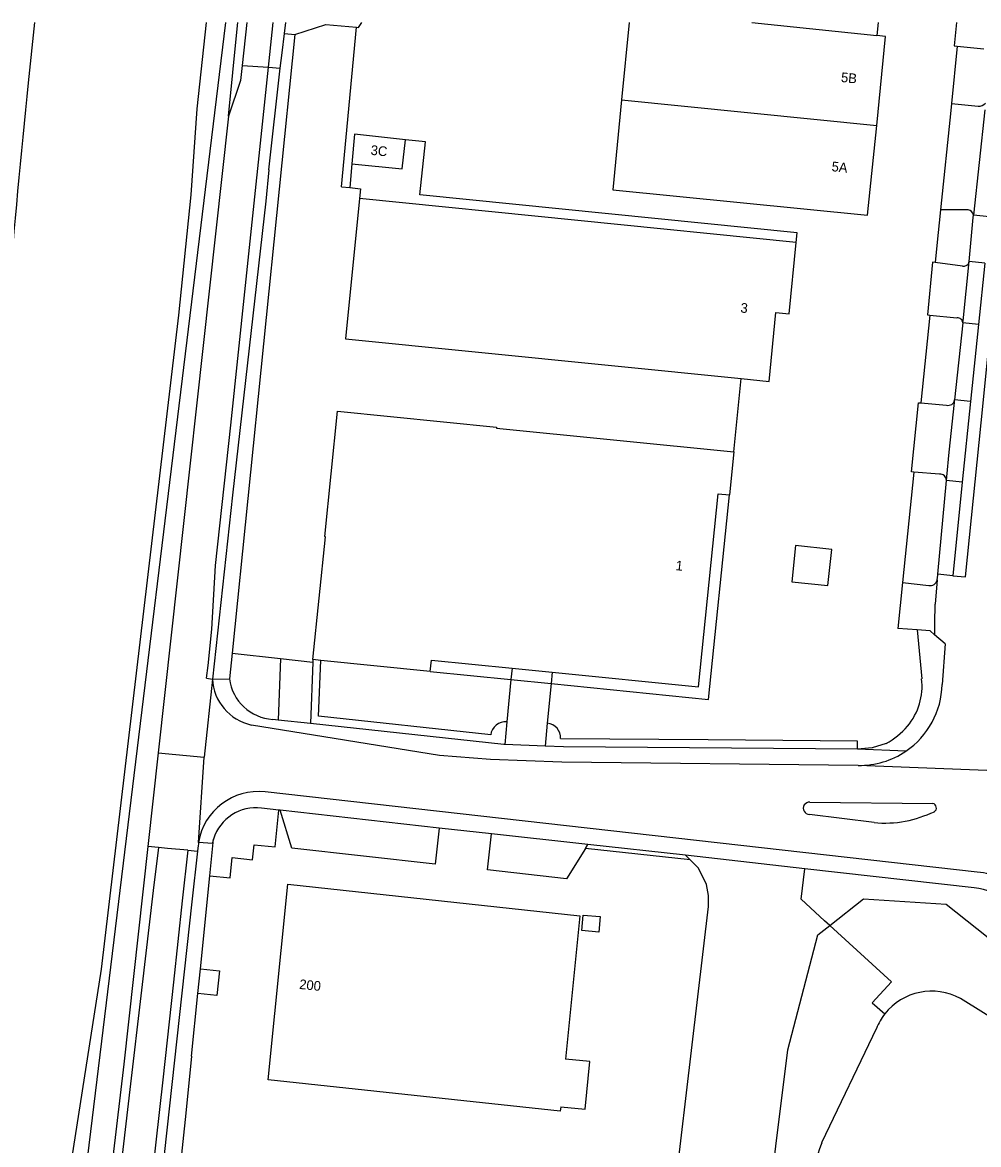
# Model space of a CAD drawing. Extents: x 194485 to 197793, y 468269 to 470822.
# Drawn here: x 195068.9 to 195187.3, y 470683.4 to 470822.3 of the extents above; entities that cross this region are included whole.
import ezdxf

# ---------------------------------------------------------------- set-up
doc = ezdxf.new("R2010")
doc.units = 0
for name, color, linetype in [('BGT begrenzing pand op maaiveld onder overbouw', 7, 'Continuous'), ('BGT grensvlak begroeid terreindeel', 7, 'Continuous'), ('BGT grensvlak onbegroeid terreindeel', 7, 'Continuous'), ('BGT grensvlak onbegroeid terreindeel LR', 7, 'Continuous'), ('BGT grensvlak ondersteunend waterdeel LR', 7, 'Continuous'), ('BGT grensvlak ondersteunend wegdeel', 7, 'Continuous'), ('BGT grensvlak pand deel overbouw', 7, 'Continuous'), ('BGT grensvlak pand op maaiveld', 7, 'Continuous'), ('BGT grensvlak pand op maaiveld LR', 7, 'Continuous'), ('BGT grensvlak vegetatieobject', 7, 'Continuous'), ('BGT grensvlak waterdeel', 7, 'Continuous'), ('BGT grensvlak wegdeel', 7, 'Continuous'), ('BGT tekst huisnummerreeks', 7, 'Continuous')]:
    doc.layers.add(name, color=color, linetype=linetype)

msp = doc.modelspace()

# ---------------------------------------------------------------- linework, layer by layer
at = {"layer": 'BGT begrenzing pand op maaiveld onder overbouw'}
msp.add_line((195129.55, 470742.33), (195134.52, 470741.83), dxfattribs=at)
for points in [[(195134.52, 470741.83), (195152.61, 470740.01), (195155.05, 470763.92), (195156.44, 470763.78)], [(195119.42, 470741.94), (195119.57, 470743.33), (195129.55, 470742.33)]]:
    msp.add_lwpolyline(points, dxfattribs=at)
at = {"layer": 'BGT grensvlak begroeid terreindeel'}
for p, q in [((195094.9, 470744.18), (195094.58, 470741.01)), ((195151.59, 470718.61), (195151.03, 470719.18))]:
    msp.add_line(p, q, dxfattribs=at)
for points in [[(195168.87, 470710.47), (195168.22, 470711.07), (195165.32, 470713.73), (195165.77, 470717.51)], [(195168.87, 470710.47), (195173.05, 470713.76), (195183.29, 470713.11), (195206.25, 470694.88), (195209.33, 470692.98), (195209.99, 470691.54)], [(195134.53, 470532.02), (195143.14, 470543.73), (195159.54, 470567.5), (195161.49, 470571.29), (195158.05, 470579.77), (195152.18, 470593.85), (195151.95, 470603.23), (195154.76, 470623.54), (195163.69, 470695.09), (195167.39, 470709.31), (195168.87, 470710.47)]]:
    msp.add_lwpolyline(points, dxfattribs=at)
at = {"layer": 'BGT grensvlak onbegroeid terreindeel'}
for p, q in [((195102.68, 470820.8), (195094.9, 470744.18)), ((195184.64, 470819.36), (195183.92, 470812.26)), ((195109.73, 470804.76), (195109.47, 470801.83)), ((195181.23, 470786.05), (195180.13, 470775.17)), ((195179.26, 470766.61), (195177.88, 470752.94)), ((195094.9, 470744.18), (195100.9, 470743.53)), ((195104.9, 470743.41), (195104.88, 470743.1)), ((195100.23, 470720.2), (195100.7, 470724.77)), ((195097.44, 470718.62), (195097.63, 470720.46)), ((195097.63, 470720.46), (195100.23, 470720.2)), ((195151.59, 470718.61), (195138.64, 470720.03)), ((195094.66, 470716.36), (195094.92, 470718.88)), ((195094.92, 470718.88), (195097.44, 470718.62)), ((195090.97, 470705.12), (195092.14, 470716.61)), ((195092.14, 470716.61), (195094.66, 470716.36)), ((195089.87, 470694.32), (195090.66, 470702.06)), ((195089.87, 470694.32), (195089.16, 470687.24)), ((195089.16, 470687.24), (195087.08, 470666.83))]:
    msp.add_line(p, q, dxfattribs=at)
for points in [[(195164.69, 470795.05), (195164.81, 470796.25), (195118.11, 470800.96), (195118.85, 470807.5), (195116.36, 470807.77)], [(195109.47, 470801.83), (195110.77, 470801.7), (195110.65, 470800.5)], [(195182.56, 470799.1), (195182.11, 470794.68), (195181.89, 470792.56)], [(195164.16, 470753.03), (195168.64, 470752.57), (195169.1, 470757.05), (195164.62, 470757.51), (195164.16, 470753.03)], [(195126.9, 470734.07), (195105.61, 470736.38), (195105.89, 470743.3)], [(195172.3, 470732.3), (195172.31, 470733.3), (195153.82, 470733.46), (195135.56, 470733.61)], [(195147.73, 470660.73), (195153.86, 470712.82), (195153.87, 470714.19), (195153.61, 470715.54), (195152.62, 470717.57), (195151.59, 470718.61)], [(195090.97, 470705.12), (195093.34, 470704.88), (195093.02, 470701.82), (195090.66, 470702.06)]]:
    msp.add_lwpolyline(points, dxfattribs=at)
for centre, start, end in [((195128.72, 470733.88), 84.4234, 174.1304), ((195133.73, 470733.7), 357.4875, 84.456)]:
    msp.add_arc(centre, 1.83, start, end, dxfattribs=at)
at = {"layer": 'BGT grensvlak onbegroeid terreindeel LR'}
for p, q in [((195108.43, 470801.93), (195110.31, 470821.68)), ((195108.43, 470801.93), (195109.47, 470801.83)), ((195156.98, 470769.12), (195157.89, 470778.2))]:
    msp.add_line(p, q, dxfattribs=at)
at = {"layer": 'BGT grensvlak ondersteunend waterdeel LR'}
msp.add_lwpolyline([(195168.87, 470710.47), (195176.49, 470703.49), (195174.12, 470700.92), (195175.67, 470699.53)], dxfattribs=at)
at = {"layer": 'BGT grensvlak ondersteunend wegdeel'}
for p, q in [((195092.14, 470716.61), (195092.6, 470721.18)), ((195090.66, 470702.06), (195090.97, 470705.12))]:
    msp.add_line(p, q, dxfattribs=at)
at = {"layer": 'BGT grensvlak pand deel overbouw'}
for p, q in [((195119.42, 470741.94), (195129.41, 470740.94)), ((195129.41, 470740.94), (195134.39, 470740.43))]:
    msp.add_line(p, q, dxfattribs=at)
msp.add_lwpolyline([(195134.39, 470740.43), (195153.86, 470738.48), (195156.44, 470763.78)], dxfattribs=at)
at = {"layer": 'BGT grensvlak pand op maaiveld'}
for p, q in [((195144.04, 470822.29), (195143.1, 470812.69)), ((195174.87, 470822.29), (195174.71, 470820.65)), ((195164.69, 470795.05), (195110.65, 470800.5)), ((195156.98, 470769.12), (195156.44, 470763.78)), ((195105.89, 470743.3), (195104.9, 470743.41)), ((195119.42, 470741.94), (195105.89, 470743.3))]:
    msp.add_line(p, q, dxfattribs=at)
for points in [[(195174.67, 470809.51), (195175.77, 470820.53), (195174.71, 470820.65)], [(195143.1, 470812.69), (195142.01, 470801.58), (195173.55, 470798.44), (195174.67, 470809.51)], [(195116.36, 470807.77), (195110.05, 470808.44), (195109.73, 470804.76)], [(195109.73, 470804.76), (195115.96, 470804.18), (195116.36, 470807.77)], [(195110.65, 470800.5), (195108.94, 470783.1), (195157.89, 470778.2)], [(195157.89, 470778.2), (195161.35, 470777.85), (195162.21, 470786.37), (195163.82, 470786.2), (195164.69, 470795.05)], [(195104.9, 470743.41), (195106.46, 470758.61), (195106.36, 470758.62), (195107.96, 470774.14), (195127.61, 470772.17), (195127.6, 470772.07), (195156.98, 470769.12)], [(195135.57, 470688.04), (195135.51, 470687.48), (195099.37, 470691.39), (195101.81, 470715.6), (195137.92, 470711.66), (195136.16, 470693.95)], [(195138.34, 470711.77), (195140.45, 470711.59), (195140.29, 470709.67), (195138.18, 470709.85), (195138.34, 470711.77)], [(195135.57, 470688.04), (195138.61, 470687.74), (195139.18, 470693.65), (195136.16, 470693.95)]]:
    msp.add_lwpolyline(points, dxfattribs=at)
at = {"layer": 'BGT grensvlak pand op maaiveld LR'}
for p, q in [((195159.22, 470822.29), (195174.71, 470820.65)), ((195143.1, 470812.69), (195174.67, 470809.51))]:
    msp.add_line(p, q, dxfattribs=at)
at = {"layer": 'BGT grensvlak vegetatieobject'}
for p, q in [((195094.1, 470822.29), (195070.12, 470625.27)), ((195094.47, 470810.67), (195095.52, 470821.5)), ((195095.52, 470821.5), (195095.6, 470822.29))]:
    msp.add_line(p, q, dxfattribs=at)
at = {"layer": 'BGT grensvlak waterdeel'}
for p, q in [((195070.43, 470822.29), (195069.65, 470814.79)), ((195174.63, 470697.75), (195167.86, 470683.58))]:
    msp.add_line(p, q, dxfattribs=at)
for points in [[(195065.26, 470625.79), (195071.88, 470661.19), (195078.75, 470705.09), (195088.31, 470786.06), (195089.82, 470800.94), (195090.58, 470811.6), (195091.71, 470822.29)], [(195065.26, 470625.79), (195071.88, 470661.19), (195078.75, 470705.09), (195088.31, 470786.06), (195089.82, 470800.94), (195090.58, 470811.6), (195091.71, 470822.29)], [(195201.88, 470689.66), (195193.26, 470696.34), (195185.03, 470701.46)]]:
    msp.add_lwpolyline(points, dxfattribs=at)
for centre, radius, start, end in [((196832.12, 470637.36), 1771.38, 174.25131, 175.12098), ((195181.5, 470694.92), 7.43, 61.6406, 141.7081), ((195181.45, 470694.95), 7.37, 141.6311, 157.6999), ((195223.07, 470664.47), 58.42, 160.9101, 168.0745)]:
    msp.add_arc(centre, radius, start, end, dxfattribs=at)
at = {"layer": 'BGT grensvlak wegdeel'}
for p, q in [((195096.71, 470822.29), (195096.13, 470816.97)), ((195099.84, 470821.08), (195099.97, 470822.29)), ((195101.38, 470820.93), (195101.53, 470822.29)), ((195099.39, 470816.73), (195099.84, 470821.08)), ((195101.38, 470820.93), (195102.68, 470820.8)), ((195184.64, 470819.36), (195187.95, 470819.03)), ((195096.13, 470816.97), (195095.92, 470815.08)), ((195096.13, 470816.97), (195099.39, 470816.73)), ((195099.39, 470816.73), (195100.86, 470816.61)), ((195099.44, 470804.04), (195100.86, 470816.61)), ((195095.92, 470815.08), (195094.47, 470810.67)), ((195183.92, 470812.26), (195183.83, 470811.4)), ((195183.92, 470812.26), (195187.23, 470811.92)), ((195094.47, 470810.67), (195085.74, 470731.87)), ((195183.83, 470811.4), (195182.56, 470799.1)), ((195188.04, 470811.46), (195186.64, 470798.44)), ((195185.98, 470799.07), (195182.56, 470799.1)), ((195188.64, 470798.23), (195186.64, 470798.44)), ((195185.28, 470792.12), (195181.89, 470792.56)), ((195185.36, 470785.35), (195186.13, 470792.67)), ((195188.05, 470792.48), (195186.13, 470792.67)), ((195188.05, 470792.48), (195187.27, 470784.9)), ((195181.23, 470786.05), (195184.61, 470785.7)), ((195185.33, 470785.1), (195185.36, 470785.35)), ((195185.33, 470785.1), (195184.32, 470775.55)), ((195187.27, 470784.9), (195185.33, 470785.1)), ((195187.27, 470784.9), (195186.3, 470775.35)), ((195184.29, 470775.24), (195184.32, 470775.55)), ((195186.3, 470775.35), (195184.32, 470775.55)), ((195180.13, 470775.17), (195183.32, 470774.9)), ((195186.3, 470775.35), (195185.27, 470765.38)), ((195182.45, 470766.36), (195179.26, 470766.61)), ((195183.31, 470765.59), (195183.35, 470766.01)), ((195182.23, 470753.96), (195183.31, 470765.59)), ((195185.27, 470765.38), (195183.31, 470765.59)), ((195185.27, 470765.38), (195184.08, 470753.79)), ((195182.16, 470753.26), (195181.89, 470750.26)), ((195182.16, 470753.26), (195182.22, 470753.84)), ((195182.22, 470753.84), (195182.23, 470753.96)), ((195184.08, 470753.79), (195182.23, 470753.96)), ((195184.08, 470753.79), (195185.66, 470753.64)), ((195177.88, 470752.94), (195177.3, 470747.26)), ((195177.88, 470752.94), (195181.11, 470752.57)), ((195179.67, 470747.1), (195177.3, 470747.26)), ((195179.67, 470747.1), (195180.24, 470741.03)), ((195183.13, 470745.36), (195181.83, 470746.48)), ((195183.13, 470745.36), (195182.77, 470740.32)), ((195100.9, 470743.53), (195100.59, 470735.92)), ((195100.9, 470743.53), (195104.88, 470743.1)), ((195104.88, 470743.1), (195104.58, 470735.48)), ((195129.55, 470742.33), (195129.41, 470740.94)), ((195092.48, 470740.98), (195091.44, 470731.32)), ((195091.71, 470741.1), (195092.48, 470740.98)), ((195092.48, 470740.98), (195094.58, 470741.01)), ((195129.41, 470740.94), (195128.9, 470735.7)), ((195134.52, 470741.83), (195134.39, 470740.43)), ((195134.39, 470740.43), (195133.91, 470735.52)), ((195100.59, 470735.92), (195099.93, 470735.99)), ((195104.58, 470735.48), (195100.59, 470735.92)), ((195128.9, 470735.7), (195128.63, 470732.88)), ((195133.91, 470735.52), (195133.63, 470732.7)), ((195133.63, 470732.7), (195128.63, 470732.88)), ((195085.74, 470731.87), (195084.45, 470720.24)), ((195085.74, 470731.87), (195091.44, 470731.32)), ((195090.75, 470720.76), (195091.44, 470731.32)), ((195178.28, 470732.06), (195172.3, 470732.3)), ((195194.47, 470729.43), (195172.38, 470730.3)), ((195187.12, 470717.1), (195098.99, 470727.01)), ((195166.4, 470725.75), (195181.61, 470725.59)), ((195100.7, 470724.77), (195098.55, 470725.01)), ((195100.83, 470724.76), (195100.7, 470724.77)), ((195120.51, 470722.55), (195100.83, 470724.76)), ((195174.34, 470723.22), (195166.35, 470724.23)), ((195126.98, 470721.83), (195120.51, 470722.55)), ((195085.8, 470720.12), (195084.45, 470720.24)), ((195090.7, 470720.38), (195090.62, 470719.69)), ((195092.46, 470720.62), (195090.75, 470720.76)), ((195138.64, 470720.03), (195138.93, 470720.5)), ((195151.03, 470719.18), (195138.93, 470720.5)), ((195089.42, 470719.8), (195090.62, 470719.69)), ((195165.77, 470717.51), (195151.03, 470719.18)), ((195186.72, 470715.13), (195165.77, 470717.51))]:
    msp.add_line(p, q, dxfattribs=at)
for points in [[(195102.68, 470820.8), (195106.49, 470822.03), (195110.31, 470821.68)], [(195110.31, 470821.68), (195110.54, 470821.65), (195110.97, 470822.29)], [(195184.54, 470822.29), (195184.24, 470819.4), (195184.64, 470819.36)], [(195185.66, 470753.64), (195187.83, 470775.13), (195189.79, 470794.58), (195192.64, 470822.29)], [(195100.86, 470816.61), (195101.11, 470818.51), (195101.38, 470820.93)], [(195092.85, 470755.05), (195094.74, 470772.43), (195096.57, 470789.72), (195099.39, 470816.73)], [(195099.44, 470804.04), (195099.06, 470800.16), (195094.96, 470763.77), (195092.48, 470740.98)], [(195186.13, 470792.67), (195186.61, 470798.14), (195186.64, 470798.44)], [(195181.89, 470792.56), (195181.58, 470792.61), (195180.96, 470786.08), (195181.23, 470786.05)], [(195179.26, 470766.61), (195179, 470766.64), (195179.86, 470775.19), (195180.13, 470775.17)], [(195183.35, 470766.01), (195183.63, 470769.1), (195184.29, 470775.24)], [(195091.71, 470741.1), (195091.95, 470742.65), (195092.37, 470747.18), (195092.85, 470755.05)], [(195181.83, 470746.48), (195181.28, 470746.95), (195179.67, 470747.1)], [(195172.38, 470730.3), (195135.69, 470730.69), (195126.87, 470731.03), (195120.56, 470731.53), (195097.28, 470735.3)], [(195128.63, 470732.88), (195128.51, 470732.89), (195104.58, 470735.48)], [(195172.3, 470732.3), (195135.93, 470732.61), (195133.63, 470732.7)], [(195175.85, 470733.01), (195174.11, 470732.46), (195172.3, 470732.3)], [(195120.51, 470722.55), (195120.02, 470718.08), (195102.29, 470720.06), (195100.83, 470724.76)], [(195138.64, 470720.03), (195136.29, 470716.26), (195126.49, 470717.36), (195126.98, 470721.83)], [(195138.93, 470720.5), (195138.55, 470720.54), (195126.98, 470721.83)], [(195085.8, 470720.12), (195085.14, 470714.81), (195083.69, 470702.46), (195082.23, 470690.17), (195080.66, 470676.72), (195078.93, 470662.44), (195077.73, 470652.53), (195076.48, 470642.25), (195075.02, 470630.1), (195073.65, 470619.21), (195072.24, 470607.94), (195070.93, 470597.45), (195069.31, 470584.95), (195067.61, 470572.76), (195065.82, 470560.53), (195064.03, 470549.27), (195062.33, 470538.21)], [(195084.45, 470720.24), (195081.48, 470693.32), (195073.43, 470624.91)], [(195089.42, 470719.8), (195086.9, 470720.03), (195085.8, 470720.12)], [(195089.42, 470719.8), (195088.73, 470713.52), (195087.63, 470703.47), (195086.34, 470691.38), (195085, 470679.62), (195083.66, 470666.84), (195082.17, 470653.12), (195080.81, 470640.54), (195079.3, 470626.36), (195078.06, 470615.15), (195076.58, 470601.6), (195075.01, 470587.02), (195073.43, 470572.81), (195071.86, 470558.25), (195070.57, 470546.85), (195069.96, 470541.4), (195069.51, 470537.39)], [(195090.62, 470719.69), (195089.93, 470713.39), (195086.19, 470679.49), (195083.36, 470652.99), (195080.49, 470626.23), (195077.77, 470601.47), (195075.61, 470581.5)]]:
    msp.add_lwpolyline(points, dxfattribs=at)
for centre, radius, start, end in [((195187.27, 470813.12), 1.2, 268.0821, 315.4321), ((195185.93, 470798.36), 0.711, 6.0964, 85.8577), ((195185.42, 470792.83), 0.728, 258.5354, 347.1583), ((195184.69, 470785.06), 0.649, 4.0887, 96.8001), ((195183.54, 470775.66), 0.787, 253.4547, 352.4646), ((195182.53, 470765.59), 0.776, 359.6228, 96.2557), ((195181.27, 470753.47), 0.917, 260.0047, 346.6427), ((195238.74, 470747.54), 56.92, 177.2621, 181.0729), ((195098.58, 470741.27), 6.11, 182.6775, 257.7337), ((195100.29, 470741.74), 5.76, 187.2777, 266.4203), ((195172.63, 470740.11), 7.66, 319.6591, 6.8851), ((195172.55, 470740.52), 10.22, 304.0857, 358.878), ((195171.24, 470741.3), 9.49, 299.099, 319.6631), ((195172.55, 470740.53), 10.23, 269.0555, 304.0808), ((195098.15, 470719.56), 7.5, 83.5855, 170.7416), ((195166.35, 470724.99), 0.763, 85.826, 269.8151), ((195181.49, 470725.03), 0.567, 303.6588, 77.8431), ((195097.86, 470719.55), 5.51, 82.8357, 162.7146), ((195173.98, 470742.45), 19.53, 282.5251, 293.6253), ((195175.65, 470737.77), 14.61, 264.8618, 280.1058), ((195097.53, 470719.65), 6.87, 170.7193, 173.9751), ((195097.88, 470719.54), 5.53, 162.7354, 168.7615), ((195186.23, 470708.82), 8.33, 41.9757, 83.8611), ((195186.29, 470709), 6.14, 42.3444, 85.9845)]:
    msp.add_arc(centre, radius, start, end, dxfattribs=at)

# ---------------------------------------------------------------- texts
at = {"layer": 'BGT tekst huisnummerreeks'}
for s, rotation, p in [('5B', 354.3, (195170.21, 470814.92)), ('3C', 353.9, (195112, 470805.91)), ('5A', 354.3, (195169.05, 470803.88)), ('3', 354.2, (195157.77, 470786.38)), ('1', 354.2, (195149.75, 470754.48)), ('200', 354.3, (195103.16, 470702.63))]:
    msp.add_text(s, height=1.2, rotation=rotation, dxfattribs=at).set_placement(p)

doc.saveas('drawing.dxf')
